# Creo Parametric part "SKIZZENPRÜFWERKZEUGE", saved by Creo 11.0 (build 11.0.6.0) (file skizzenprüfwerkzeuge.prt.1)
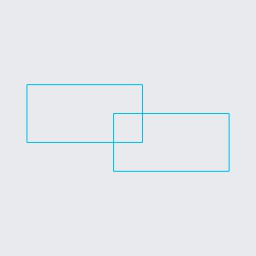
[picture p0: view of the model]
Units: millimeter Kilogram Sec (mmKs); MM, KILOGRAM, SECS
Materials in the file: S235JRG2

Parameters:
  BENENNUNG = "XXX"
  DATUM = "XX.XX.XX"
  ERSTELLER = "arinda"
  TEILETYP = "Fertigungsteil"
  PTC_MASTER_MATERIAL = "S235JRG2"
  SELECT_EN_NAME = "S235JRG2"
  SELECT_DIN_NAME = "RSt37-2"
  SELECT_DIN_NUMBER = "1.0038"
  SELECT_ASTM_NAME = "A 283 M Grade 2"
  MATERIAL_GROUP = "ME_ST_Baustahl"
  STANDARD_EN_DELIVERYSPEC = "DIN EN 10025"
  STANDARD_DIN_DELIVERYSPEC = "DIN 17100"

Other parameters: MASSE

Created from: ARINDA-STARTTEIL.PRT

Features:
  1. coordinate system "CS0"
  2. datum plane "DTM1", "T_RECHTS_Y-Z"
  3. datum plane "DTM2", "T_OBEN_X-Z"
  4. datum plane "DTM3", "T_VORNE_X-Y"
  5. datum axis "T_X-ACHSE"
  6. datum axis "A_1"
  7. datum axis "A_2"
  8. sketch "Skizze 1"

Other named items: T_BASIC, T_Y-ACHSE, T_Z-ACHSE

Layers: 00_STD-ACHSEN, 00_STD-EBENEN, 00_STD-KOORDSYS, 01_KURVEN, KURVENELEMENTE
